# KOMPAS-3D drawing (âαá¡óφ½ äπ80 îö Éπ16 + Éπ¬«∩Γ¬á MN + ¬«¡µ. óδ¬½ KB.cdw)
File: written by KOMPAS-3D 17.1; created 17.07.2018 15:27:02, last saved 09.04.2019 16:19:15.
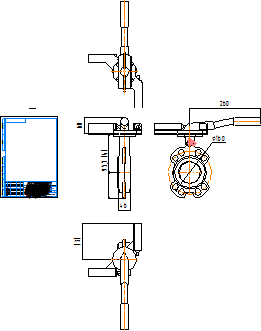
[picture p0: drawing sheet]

Sheet 1: A4, portrait

Title block, sheet 1: name: Гранвэл Ду80 МФ Ру16 + / Рукоятка MN + конц. выкл KB; material: Внимание! Данный продукт является объектом авторского права ООО «Торговый Дом АДЛ». / Запрещается изменение, копирование, распространение / (в том числе путем копирования на другие сайты и ресурсы в Интернете) / или любое иное использование информации и объектов без предварительного / согласия правообладателя (ООО «Торговый Дом АДЛ»).; mass: 7,7; sheets: 1; organisation: ООО "Торговый дом АДЛ"; sheet format: A4; stored path: \\adlc.lan\data\АДЛ_ПКД\3D-модели\ADL production\Дисковые поворотные затворы ГРАНВЭЛ\межфланцевый с рукояткой MN и конц. выкл\KOMPAS 2D\Гранвэл Ду80 МФ Ру16 + Рукоятка MN + конц. выкл KB.cdw

Views: Вид 1, Проекционный вид 2, Проекционный вид 3, Проекционный вид 4
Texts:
  kka
  adl
Dimensions and other numbers on the sheet: 46; 60; 95,7; 141; 160; 260; 131; 1:1; 1; 7,7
